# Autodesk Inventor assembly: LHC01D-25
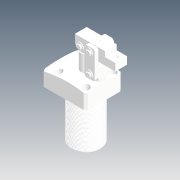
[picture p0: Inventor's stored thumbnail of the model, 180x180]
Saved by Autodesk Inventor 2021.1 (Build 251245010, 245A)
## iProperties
Created: 2019-04
Part Number: LHC01D-25
Description: STEP AP214
Document SubType Name: Assembly
Designer: user
Title: LHC01D-25.STEP
Revision Number: ÈÎºÎ
Sending System: SolidWorks 2016
Preprocessor: SwSTEP 2.0
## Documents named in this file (12)
- D:\Vault_2016\Projekty\Clamptek\Hydraulic\LHC01D\Inventor\LHC01D-25\LHC01D-25.iam
- D:\Vault_2016\Projekty\Clamptek\Hydraulic\LHC01D\Inventor\LHC01D-25\LHC01D-25-01.ipt
- D:\Vault_2016\Projekty\Clamptek\Hydraulic\LHC01D\Inventor\LHC01D-25\CPLCU-25-05.ipt
- D:\Vault_2016\Projekty\Clamptek\Hydraulic\LHC01D\Inventor\LHC01D-25\LHC01D25»îÈû¸Ë.ipt
- D:\Vault_2016\Projekty\Clamptek\Hydraulic\LHC01D\Inventor\LHC01D-25\CPLCU-25-01.ipt
- D:\Vault_2016\Projekty\Clamptek\Hydraulic\LHC01D\Inventor\LHC01D-25\CPLCU-25-02.ipt
- D:\Vault_2016\Projekty\Clamptek\Hydraulic\LHC01D\Inventor\LHC01D-25\CPLCU-25-09.ipt
- D:\Vault_2016\Projekty\Clamptek\Hydraulic\LHC01D\Inventor\LHC01D-25\CPLCU-25-03.ipt
- D:\Vault_2016\Projekty\Clamptek\Hydraulic\LHC01D\Inventor\LHC01D-25\CPLCU-25-04.ipt
- D:\Vault_2016\Projekty\Clamptek\Hydraulic\LHC01D\Inventor\LHC01D-25\LHC01D-32-01.ipt
- D:\Vault_2016\Projekty\Clamptek\Hydraulic\LHC01D\Inventor\LHC01D-25\¶ÂÍ·.ipt
- D:\Vault_2016\Projekty\Clamptek\Hydraulic\LHC01D\Inventor\LHC01D-25\M4ningjin.ipt
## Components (24 placed, 24 different names)
1. LHC01D-25-01_1
2. CPLCU-25-05_2
3. LHC01D25»îÈû¸Ë_3
4. CPLCU-25-01_4
5. CPLCU-25-02_5
6. CPLCU-25-02_6
7. CPLCU-25-09_7
8. CPLCU-25-09_8
9. CPLCU-25-09_9
10. CPLCU-25-09_10
11. CPLCU-25-09_11
12. CPLCU-25-09_12
13. CPLCU-25-03_13
14. CPLCU-25-04_14
15. CPLCU-25-04_15
16. LHC01D-32-01_16
17. LHC01D-32-01_17
18. LHC01D-32-01_18
19. LHC01D-32-01_19
20. LHC01D-32-01_20
21. LHC01D-32-01_21
22. ¶ÂÍ·_22
23. ¶ÂÍ·_23
24. M4ningjin_24
